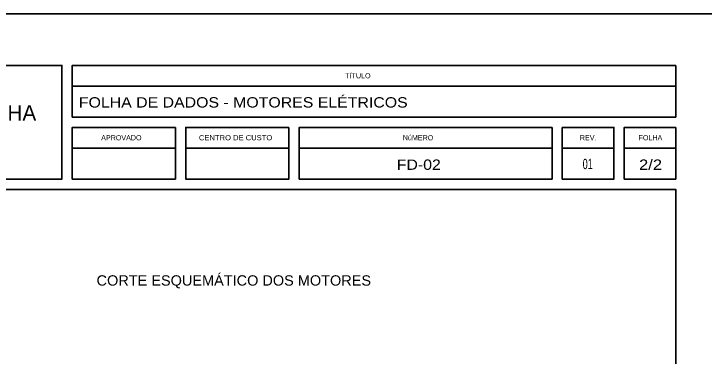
# Model space of a CAD drawing. Extents: x -4160 to -2690, y -474 to 714.
# Drawn here: x -3669.1 to -3535.3, y -242.8 to -176.5 of the extents above; entities that cross this region are included whole.
import ezdxf
from ezdxf.enums import TextEntityAlignment as Align

# ---------------------------------------------------------------- set-up
doc = ezdxf.new("R2010")
doc.units = 0
doc.header["$LTSCALE"] = 0.56
doc.layers.add('1', color=7, linetype='Continuous', lineweight=25)
doc.layers.add('5', color=7, linetype='Continuous', lineweight=35)

msp = doc.modelspace()

# ---------------------------------------------------------------- linework, layer by layer
at = {"layer": '5'}
for p, q in [((-3657.7641, -190.52), (-3540.7642, -190.52)), ((-3657.7641, -202.5199), (-3637.7641, -202.5199)), ((-3635.7641, -202.5199), (-3615.7641, -202.5199)), ((-3613.7641, -202.5199), (-3564.7642, -202.5199)), ((-3562.7642, -202.5199), (-3552.7642, -202.5199)), ((-3550.7642, -202.5199), (-3540.7642, -202.5199))]:
    msp.add_line(p, q, dxfattribs=at)
at = {"layer": '5', "lineweight": 25}
for points in [[(-3739.7642, -176.52), (-3529.7642, -176.52), (-3739.7642, -176.52)], [(-3739.764, -176.52), (-3529.7642, -176.52), (-3529.7642, -473.5197)]]:
    msp.add_lwpolyline(points, dxfattribs=at)
at = {"layer": '5'}
for points in [[(-3714.764, -208.5199), (-3714.764, -186.52), (-3659.7641, -186.52), (-3659.7641, -208.5199)], [(-3540.7642, -186.52), (-3657.7641, -186.52), (-3657.7641, -196.5199), (-3540.7642, -196.5199)], [(-3637.7641, -198.5199), (-3657.7641, -198.5199), (-3657.7641, -208.5199), (-3637.7641, -208.5199)], [(-3615.7641, -198.5199), (-3635.7641, -198.5199), (-3635.7641, -208.5199), (-3615.7641, -208.5199)], [(-3564.7642, -198.5199), (-3613.7641, -198.5199), (-3613.7641, -208.5199), (-3564.7642, -208.5199)], [(-3562.7642, -198.5199), (-3552.7642, -198.5199), (-3552.7642, -208.5199), (-3562.7642, -208.5199)], [(-3540.7642, -198.5199), (-3550.7642, -198.5199), (-3550.7642, -208.5199), (-3540.7642, -208.5199)], [(-3714.764, -463.5197), (-3714.764, -210.5199), (-3540.7642, -210.5199), (-3540.7642, -463.5197)]]:
    msp.add_lwpolyline(points, close=True, dxfattribs=at)

# ---------------------------------------------------------------- texts
at = {"layer": '1'}
for s, width, p in [('FOLHA DE DADOS - MOTORES ELÉTRICOS', 1.15, (-3624.607, -194.661)), ('FD-02', 1.15, (-3590.5884, -206.7222)), ('01', 0.65, (-3557.8456, -206.5911)), ('2/2', 1.2, (-3545.6652, -206.7222)), ('CORTE ESQUEMÁTICO DOS MOTORES', 1.05, (-3626.4406, -229.1356))]:
    msp.add_text(s, height=2, dxfattribs=dict(at, width=width)).set_placement(p, align=Align.CENTER)
at = {"layer": '5'}
for s, height, p in [('TíTULO', 1, (-3602.3849, -189.0085)), ('CONSóRCIO NORONHA', 3, (-3687.4748, -197.2042)), ('APROVADO', 1, (-3648.2383, -201.0028)), ('REV.', 1, (-3557.7449, -201.0071)), ('FOLHA', 1, (-3545.6813, -201.0071))]:
    msp.add_text(s, height=height, dxfattribs=at).set_placement(p, align=Align.CENTER)
for s, width, p in [('CENTRO DE CUSTO', 1.1, (-3626.0933, -201.0028)), ('NúMERO', 0.95, (-3590.7234, -201.0071))]:
    msp.add_text(s, height=1, dxfattribs=dict(at, width=width)).set_placement(p, align=Align.CENTER)

doc.saveas('drawing.dxf')
